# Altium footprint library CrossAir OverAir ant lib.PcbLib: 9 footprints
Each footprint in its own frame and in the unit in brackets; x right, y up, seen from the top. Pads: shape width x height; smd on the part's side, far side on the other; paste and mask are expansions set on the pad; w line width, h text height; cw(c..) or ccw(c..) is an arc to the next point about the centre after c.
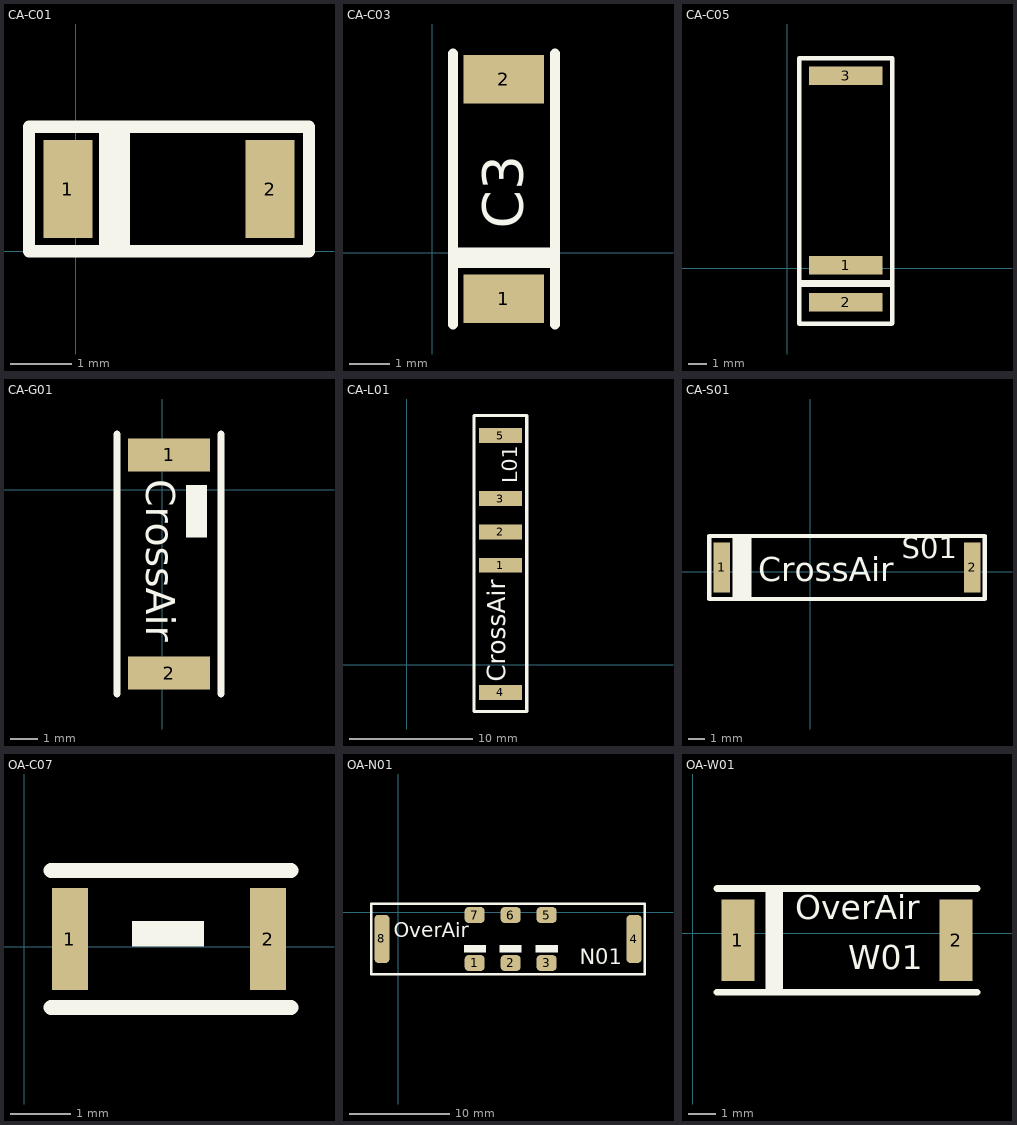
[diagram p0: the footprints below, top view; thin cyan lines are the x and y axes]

## CA-C01 [mm] "CA-C01  2.4G SMD antenna"
height 0.4
pads (2):
  rect 0.8x1.6 smd: 1(-0.127,1.016) 2(3.175,1.016)
Top Overlay:
  rectangle: 0.381,0 0.889,2.032
  lines w0.2: -0.762,0 -0.762,2.032 3.81,2.032 3.81,0 -0.762,0

## CA-C03 [mm] "CA-C03  2.4G SMD antenna"
height 1
pads (2):
  rect 2x1.2 smd: 1(1.778,-1.143) 2(1.778,4.318)
Top Overlay:
  rectangle: 0.508,-0.381 2.921,0.127
  lines w0.254: 0.508,-1.778 0.508,4.953 ; 3.048,-1.778 3.048,4.953
  text "C3" at 2.25,0.6 h1

## CA-C05 [mm] "CA-C05 2.4G SMD antenna"
height 3
pads (3):
  rect 4x1 smd: 1(3.187,0.167) 2(3.187,-1.833) 3(3.187,10.467)
Top Overlay:
  rectangle: 0.662,-1.016 5.842,-0.635
  lines w0.254: 5.687,-3.008 0.662,-3.008 0.662,11.417 5.712,11.417 5.712,-2.983

## CA-G01 [mm] "CA-G01 GPS BD GNSS antenna"
height 1
pads (2):
  rect 3x1.2 smd: 1(0.254,1.27) 2(0.254,-6.731)
Top Overlay:
  rectangle: 0.875,-1.75 1.65,0.175
  lines w0.254: -1.651,-7.493 -1.651,2.032 ; 2.159,-7.493 2.159,2.032
  text "CrossAir" at -0.925,0.375 h1.8

## CA-L01 [mm] "CA-L01 LTE antenna"
height 1.6
pads (5):
  rect 3.5x1.2 smd: 1(7.578,8.057) 2(7.578,10.757) 3(7.571,13.45) 4(7.578,-2.243) 5(7.578,18.557)
Top Overlay:
  lines w0.254: 5.428,-3.793 5.428,20.182 9.703,20.182 9.703,-3.793 5.428,-3.793
  text "CrossAir" at 8.45,-1.375 h2.5
  text "L01" at 8.925,14.7 h1.2

## CA-S01 [mm] "CA-S01 NB lora antenna"
height 1
pads (2):
  rect 1x3 smd: 1(-5.334,0.254) 2(9.779,0.254)
Top Overlay:
  rectangle: -4.699,-1.651 -3.556,2.159
  lines w0.254: -6.096,-1.651 10.541,-1.651 10.541,2.159 -6.096,2.159 -6.096,-1.651
  text "S01" at 5.525,0.375 h2.2
  text "CrossAir" at -3.125,-1.075 h2.5

## OA-C07 [mm] "2.4G SMD chip ant"
height 1.2
pads (2):
  rect 0.6x1.7 smd: 1(0.762,0.127) 2(4.064,0.127)
Top Overlay:
  rectangle: 1.8,0 3,0.425
  lines w0.254: 0.445,-1.016 4.445,-1.016 ; 0.445,1.27 4.445,1.27

## OA-N01 [mm] "5G 4G 3G 2G SMD CHIP ANTENNA"
pads (8):
  rrect50% 2x1.6 smd: 1(7.625,-5.075) 2(11.225,-5.075) 3(14.825,-5.075) 5(14.825,-0.275) 6(11.225,-0.275) 7(7.625,-0.275)
  rrect50% 1.5x4.8 smd: 4(23.575,-2.675) 8(-1.651,-2.667)
Top Overlay:
  rectangle: 13.725,-4.05 15.95,-3.275
  rectangle: 10.1,-4.05 12.325,-3.275
  rectangle: 6.55,-4.05 8.775,-3.275
  pour cut-out: 13.4,-2.275
  lines w0.254: -2.725,-6.225 -2.725,0.875 24.65,0.875 24.65,-6.225 -2.725,-6.225
  text "N01" at 18.125,-5.2 h1.52
  text "OverAir" at -0.45,-3 h2.5

## OA-W01 [mm] "2.4G 5G WIFI SMD CHIP ANTENNA"
pads (2):
  rect 1.2x3 smd: 1(1.651,-0.254) 2(9.652,-0.254)
Top Overlay:
  region: 3.302,-2.159 3.302,1.651 2.667,1.651 2.667,-2.159
  lines w0.254: 0.889,-2.159 10.414,-2.159 ; 0.889,1.651 10.414,1.651
  text "OverAir" at 3.75,0.225 h1.52
  text "W01" at 5.7,-1.6 h1.52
